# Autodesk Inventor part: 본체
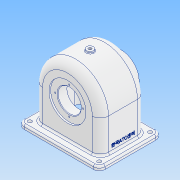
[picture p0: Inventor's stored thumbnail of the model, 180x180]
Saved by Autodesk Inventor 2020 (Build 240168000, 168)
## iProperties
Created: 2022-09
Part Number: 본체
Material: 알루미늄 6061
Document SubType Name: Modeling
Designer: user
Density: 2.7 g/cm^3
Appearance: 알루미늄 - 평지
Mass: 752.477 g
Surface Area: 994.185 cm^2
Volume: 278.695 cm^3
Author: user
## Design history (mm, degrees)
sketch "스케치1"
  geometry: L1 (-57, 0)-(-57, -57); L2 (57, 0)-(57, -57); L3 (57, -57)-(-57, -57); A1 r 57 centre (0, 0) between (-57, 0) and (57, 0); 1 further point
  constraints: 6 end point, 2 point on circle, 2 vertical, 1 centre point, 1 coincident, 1 perpendicular, 1 tangent
  dimensions: "d0" = 114 diameter of A1; "d1" = 57 distance from line of point (0, 0) L3; "d2" = 114 distance of L2.end L1.end
extrude "돌출1" new body sketch "스케치1" stored distance "d3" = 78; taper "d4" = 0 deg
feature "쉘1" dims "d5" = 5
sketch "스케치2"
  geometry: L1 (5, -73)-(5, -5) reference; L2 (5, -5)-(109, -5) reference; L3 (-13, -93)-(127, -93); L4 (127, -93)-(127, 15); L5 (127, 15)-(-13, 15); L6 (-13, 15)-(-13, -93); 3 further points
  constraints: 8 end point, 2 midpoint, 2 parallel, 1 horizontal, 1 horizontal alignment, 1 perpendicular, 1 vertical alignment
  dimensions: "d6" = 140 distance of L4.end L5.end; "d7" = 108 distance of L5.end L3.start
extrude "돌출2" join sketch "스케치2" distance "d8" = 7; taper "d9" = 0 deg
sketch "스케치3"
  geometry: C1 r 31 at (0, 0); A1 r 57 centre (0, 0) between (57, 0) and (-57, 0) reference
  constraints: 1 centre point, 1 coincident
  dimensions: "d10" = 62 diameter of C1
extrude "돌출3" join sketch "스케치3" distance "d11" = 15; taper "d12" = 0 deg
sketch "스케치4"
  geometry: C1 r 31 at (0, 0) reference; C2 r 20 at (0, 0)
  constraints: 1 centre point, 1 coincident
  dimensions: "d13" = 40 diameter of C2
extrude "돌출4" cut sketch "스케치4" distance "d14" = 16; taper "d15" = 0 deg
sketch "스케치5"
  geometry: L1 (52, 34)-(0, 34) reference; L2 (36.083, 34)-(28, 20); L3 (28, 20)-(0, 20); L4 (0, 20)-(0, 34); 1 further point
  constraints: 6 end point, 1 parallel, 1 perpendicular, 1 point on line
  dimensions: "d16" = 56 diameter of L2.end L4; "d17" = 60 deg angle of L3 L2; "d18" = 14 distance of L3.end L1.end
revolve "회전1" sketch "스케치5" stored, may be unused: angle "d19" = 90 deg
sketch "스케치6"
  geometry: C1 r 28 at (0, 0) reference; C2 r 20 at (0, 0)
  constraints: 1 centre point, 1 coincident
  dimensions: "d20" = 40 diameter of C2
extrude "돌출5" cut sketch "스케치6" distance "d21" = 16; taper "d22" = 0 deg
sketch "스케치7"
  geometry: C1 r 20 at (0, 0) reference; C2 r 32 at (0, 0)
  constraints: 1 centre point, 1 coincident
  dimensions: "d23" = 64 diameter of C2
extrude "돌출6" cut sketch "스케치7" extent not by distance; stored distance "d24" = 75; taper "d25" = 0 deg
sketch "스케치8"
  geometry: C1 r 20 at (0, 0) reference; C2 r 17.5 at (0, 0)
  constraints: 1 centre point, 1 coincident
  dimensions: "d26" = 35 diameter of C2
extrude "돌출7" cut sketch "스케치8" distance "d27" = 16; taper "d28" = 0 deg
node "작업 평면1"
sketch "스케치9"
  geometry: C1 r 6 at (0, 0); 1 further point
  constraints: 1 centre point, 1 coincident
  dimensions: "d30" = 12 diameter of C1
extrude "돌출8" join sketch "스케치9" stored distance "d31" = 16; taper "d32" = 0 deg
sketch "스케치10"
  geometry: C1 r 6 at (0, 0) reference
hole "구멍1" sketch "스케치10" at (0, 0) diameter "d33" = 5.1881; stored, may be unused: countersink angle "d37" = 90 deg, drill point angle "d39" = 118 deg; dims "d34" = 36.75, "d35" = 8, "d36" = 4.4, "d38" = 16
sketch "스케치11" dims "d40" = 48
  geometry: C1 r 20 at (0, 0) reference; C2 r 31 at (0, 0) reference; 5 further points
  constraints: 2 vertical alignment, 1 coincident, 7 other
  dimensions: "d43" = 360 deg dimension on C1.centre point (0, 24) (derived)
hole "구멍2" sketch "스케치11" at (0, 24), (-24, 0), (0, -24), (24, 0) diameter "d45" = 2.459; stored, may be unused: countersink angle "d49" = 90 deg, drill point angle "d51" = 118 deg; dims "d46" = 7, "d47" = 8, "d48" = 4.4, "d50" = 9
sketch "스케치12"
  geometry: C1 r 20 at (0, 0) reference; C2 r 32 at (0, 0) reference; C3 r 24 at (0, 0); C4 r 1.23 at (0, 24) reference; 7 further points
  constraints: 5 coincident, 1 centre point, 9 other
  dimensions: "d52" = 48 diameter of C3; "d55" = 360 deg dimension on C1.centre C4.centre (derived)
hole "구멍3" sketch "스케치12" at (0, 24), (-24, 0), (0, -24), (24, 0) diameter "d57" = 2.459; stored, may be unused: countersink angle "d61" = 90 deg, drill point angle "d63" = 118 deg; dims "d58" = 7, "d59" = 8, "d60" = 4.4, "d62" = 9
fillet "모깎기4" dims "d74" = 3
chamfer "모따기1" distance "d77" = 1; stored, may be unused: second distance "d78" = 2, angle "d79" = 45 deg
node "작업 평면2"
fillet "모깎기6" dims "d84" = 14
sketch "스케치17"
  geometry: L1 (0, -64)-(114, -64) reference; L2 (88.072, -64)-(86.313, -64); L3 (86.313, -64)-(86.313, -73.59); L4 (86.313, -73.59)-(88.072, -73.59); L5 (88.072, -73.59)-(88.072, -64); L6 (109, -5)-(109, -73) reference; L7 (114, -64)-(114, -14) reference; L8 (5, -5)-(109, -5) reference; L9 (14, 0)-(100, 0) reference; L10 (5, -73)-(5, -5) reference; L11 (0, -64)-(0, -14) reference; L12 (109, -73)-(5, -73) reference; L13 (100, -78)-(14, -78) reference; C1 r 2.594 at (57, -39) reference; 2 further points
  constraints: 8 end point, 2 parallel, 1 horizontal, 1 perpendicular, 1 point on line
extrude "돌출9" cut sketch "스케치17" distance "d85" = 7; taper "d86" = 0 deg
sketch "스케치18"
  geometry: L1 (109, -64)-(5, -64) reference; L2 (109, -73)-(5, -73) reference; L3 (109, -64)-(109, -73) reference; L4 (5, -73)-(5, -64) reference; A1 r 14 centre (14, -64) between (0, -64) and (14, -78) reference; 1 further point
extrude "돌출10" cut sketch "스케치18" distance "d87" = 7; taper "d88" = 0 deg
fillet "모깎기7" dims "d89" = 9
fillet "모깎기8" dims "d90" = 10
sketch "스케치19"
  geometry: A1 r 10 centre (-3, 83) between (-3, 93) and (-13, 83) reference; A2 r 10 centre (-3, -5) between (-13, -5) and (-3, -15) reference; A3 r 10 centre (117, -5) between (117, -15) and (127, -5) reference; A4 r 10 centre (117, 83) between (127, 83) and (117, 93) reference; 1 further point
hole "구멍5" sketch "스케치19" at (117, -5), (117, 83), (-3, 83), (-3, -5) diameter "d91" = 6.6; stored, may be unused: countersink angle "d95" = 90 deg, drill point angle "d97" = 118 deg; dims "d92" = 7, "d93" = 8, "d94" = 4.4, "d96" = 9
fillet "모깎기9" dims "d98" = 3, "d99" = 1
sketch "스케치20"
  geometry: L1 (-14, 0)-(-14, -54) reference; L2 (-19, -64)-(-29, -64) reference; 2 further points
  constraints: 1 other
  dimensions: "d100" = 39 distance from line of point (25, -47) L1; "d101" = 17 distance from line of L2 point (25, -47)
feature "엠보싱2" sketch "스케치20" dims "d0" = 114, "d1" = 57, "d2" = 114, "d102" = 0.5, "d103" = 0
node "솔리드1"
feature "A9D066F2-1C7D-4E18-AEED-F7BC21143FA4" dims "d45" = 2.459, "d46" = 7, "d47" = 8, "d48" = 4.4, "d49" = 90 deg, "d50" = 9, "d51" = 118 deg
